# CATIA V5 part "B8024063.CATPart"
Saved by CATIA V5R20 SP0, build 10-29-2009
Part number: B8024063
Revision: 7
Definition: design
Nomenclature: B8024063
Source: made
Description: NOT SPECIFIED
Bounding box of the stored display mesh (mm): x -33 to 33, y -33 to 33, z -12 to 63
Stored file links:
  C:\Users\Utente\Desktop\3D files B802\B8024063.CATPart
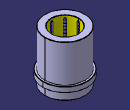
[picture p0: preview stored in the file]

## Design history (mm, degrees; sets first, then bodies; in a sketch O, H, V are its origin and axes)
Body1 "MANIFOLD_SOLID_BREP #38" (main body)
  Solid1: solid without history
Body2 "MANIFOLD_SOLID_BREP #76"
  Solid2: solid without history
Body3 "MANIFOLD_SOLID_BREP #114"
  Solid3: solid without history
Body4 "MANIFOLD_SOLID_BREP #152"
  Solid4: solid without history
Body5 "MANIFOLD_SOLID_BREP #190"
  Solid5: solid without history
Body6 "MANIFOLD_SOLID_BREP #228"
  Solid6: solid without history
Body7 "MANIFOLD_SOLID_BREP #266"
  Solid7: solid without history
Body8 "MANIFOLD_SOLID_BREP #304"
  Solid8: solid without history
Body9 "MANIFOLD_SOLID_BREP #2384"
  Solid9: solid without history
Body10 "MANIFOLD_SOLID_BREP #2422"
  Solid10: solid without history
Body11 "MANIFOLD_SOLID_BREP #2460"
  Solid11: solid without history
Body12 "MANIFOLD_SOLID_BREP #2498"
  Solid12: solid without history
Body13 "MANIFOLD_SOLID_BREP #2536"
  Solid13: solid without history
Body14 "MANIFOLD_SOLID_BREP #2574"
  Solid14: solid without history
Body15 "MANIFOLD_SOLID_BREP #2612"
  Solid15: solid without history
Body16 "MANIFOLD_SOLID_BREP #2650"
  Solid16: solid without history
Body17 "MANIFOLD_SOLID_BREP #2688"
  Solid17: solid without history
Body18 "MANIFOLD_SOLID_BREP #2726"
  Solid18: solid without history
Body19 "MANIFOLD_SOLID_BREP #2764"
  Solid19: solid without history
Body20 "MANIFOLD_SOLID_BREP #2802"
  Solid20: solid without history
Body21 "MANIFOLD_SOLID_BREP #2840"
  Solid21: solid without history
Body22 "MANIFOLD_SOLID_BREP #2878"
  Solid22: solid without history
Body23 "MANIFOLD_SOLID_BREP #2916"
  Solid23: solid without history
Body24 "MANIFOLD_SOLID_BREP #2954"
  Solid24: solid without history
Body25 "MANIFOLD_SOLID_BREP #2992"
  Solid25: solid without history
Body26 "MANIFOLD_SOLID_BREP #3030"
  Solid26: solid without history
Body27 "MANIFOLD_SOLID_BREP #3068"
  Solid27: solid without history
Body28 "MANIFOLD_SOLID_BREP #3106"
  Solid28: solid without history
Body29 "MANIFOLD_SOLID_BREP #3144"
  Solid29: solid without history
Body30 "MANIFOLD_SOLID_BREP #3182"
  Solid30: solid without history
Body31 "MANIFOLD_SOLID_BREP #3220"
  Solid31: solid without history
Body32 "MANIFOLD_SOLID_BREP #3258"
  Solid32: solid without history
Body33 "MANIFOLD_SOLID_BREP #3296"
  Solid33: solid without history
Body34 "MANIFOLD_SOLID_BREP #3334"
  Solid34: solid without history
Body35 "MANIFOLD_SOLID_BREP #3372"
  Solid35: solid without history
Body36 "MANIFOLD_SOLID_BREP #3410"
  Solid36: solid without history
Body37 "MANIFOLD_SOLID_BREP #3448"
  Solid37: solid without history
Body38 "MANIFOLD_SOLID_BREP #3486"
  Solid38: solid without history
Body39 "MANIFOLD_SOLID_BREP #3524"
  Solid39: solid without history
Body40 "MANIFOLD_SOLID_BREP #3562"
  Solid40: solid without history
Body41 "MANIFOLD_SOLID_BREP #3600"
  Solid41: solid without history
Body42 "MANIFOLD_SOLID_BREP #3638"
  Solid42: solid without history
Body43 "MANIFOLD_SOLID_BREP #3676"
  Solid43: solid without history
Body44 "MANIFOLD_SOLID_BREP #3714"
  Solid44: solid without history
Body45 "MANIFOLD_SOLID_BREP #3752"
  Solid45: solid without history
Body46 "MANIFOLD_SOLID_BREP #3790"
  Solid46: solid without history
Body47 "MANIFOLD_SOLID_BREP #3828"
  Solid47: solid without history
Body48 "MANIFOLD_SOLID_BREP #3866"
  Solid48: solid without history
Body49 "MANIFOLD_SOLID_BREP #3904"
  Solid49: solid without history
Body50 "MANIFOLD_SOLID_BREP #3942"
  Solid50: solid without history
Body51 "MANIFOLD_SOLID_BREP #3980"
  Solid51: solid without history
Body52 "MANIFOLD_SOLID_BREP #4018"
  Solid52: solid without history
Body53 "MANIFOLD_SOLID_BREP #4056"
  Solid53: solid without history
Body54 "MANIFOLD_SOLID_BREP #4094"
  Solid54: solid without history
Body55 "MANIFOLD_SOLID_BREP #4132"
  Solid55: solid without history
Body56 "MANIFOLD_SOLID_BREP #4170"
  Solid56: solid without history
Body57 "MANIFOLD_SOLID_BREP #4208"
  Solid57: solid without history
Body58 "MANIFOLD_SOLID_BREP #4246"
  Solid58: solid without history
Body59 "MANIFOLD_SOLID_BREP #4284"
  Solid59: solid without history
Body60 "MANIFOLD_SOLID_BREP #4322"
  Solid60: solid without history
Body61 "MANIFOLD_SOLID_BREP #4360"
  Solid61: solid without history
Body62 "MANIFOLD_SOLID_BREP #4398"
  Solid62: solid without history
Body63 "MANIFOLD_SOLID_BREP #4436"
  Solid63: solid without history
Body64 "MANIFOLD_SOLID_BREP #4474"
  Solid64: solid without history
Body65 "MANIFOLD_SOLID_BREP #4512"
  Solid65: solid without history
Body66 "MANIFOLD_SOLID_BREP #4550"
  Solid66: solid without history
Body67 "MANIFOLD_SOLID_BREP #4588"
  Solid67: solid without history
Body68 "MANIFOLD_SOLID_BREP #4626"
  Solid68: solid without history
Body69 "MANIFOLD_SOLID_BREP #4664"
  Solid69: solid without history
Body70 "MANIFOLD_SOLID_BREP #4702"
  Solid70: solid without history
Body71 "MANIFOLD_SOLID_BREP #4740"
  Solid71: solid without history
Body72 "MANIFOLD_SOLID_BREP #4778"
  Solid72: solid without history
Body73 "MANIFOLD_SOLID_BREP #4816"
  Solid73: solid without history
Body74 "MANIFOLD_SOLID_BREP #4854"
  Solid74: solid without history
Body75 "MANIFOLD_SOLID_BREP #4892"
  Solid75: solid without history
Body76 "MANIFOLD_SOLID_BREP #4930"
  Solid76: solid without history
Body77 "MANIFOLD_SOLID_BREP #4968"
  Solid77: solid without history
Body78 "MANIFOLD_SOLID_BREP #5006"
  Solid78: solid without history
Body79 "MANIFOLD_SOLID_BREP #5044"
  Solid79: solid without history
Body80 "MANIFOLD_SOLID_BREP #5082"
  Solid80: solid without history
Body81 "MANIFOLD_SOLID_BREP #5120"
  Solid81: solid without history
Body82 "MANIFOLD_SOLID_BREP #5158"
  Solid82: solid without history
Body83 "MANIFOLD_SOLID_BREP #5196"
  Solid83: solid without history
Body84 "MANIFOLD_SOLID_BREP #5234"
  Solid84: solid without history
Body85 "MANIFOLD_SOLID_BREP #5272"
  Solid85: solid without history
Body86 "MANIFOLD_SOLID_BREP #5310"
  Solid86: solid without history
Body87 "MANIFOLD_SOLID_BREP #5348"
  Solid87: solid without history
Body88 "MANIFOLD_SOLID_BREP #5386"
  Solid88: solid without history
Body89 "MANIFOLD_SOLID_BREP #5424"
  Solid89: solid without history
Body90 "MANIFOLD_SOLID_BREP #5462"
  Solid90: solid without history
Body91 "MANIFOLD_SOLID_BREP #5500"
  Solid91: solid without history
Body92 "MANIFOLD_SOLID_BREP #5538"
  Solid92: solid without history
Body93 "MANIFOLD_SOLID_BREP #5576"
  Solid93: solid without history
Body94 "MANIFOLD_SOLID_BREP #5614"
  Solid94: solid without history
Body95 "MANIFOLD_SOLID_BREP #5652"
  Solid95: solid without history
Body96 "MANIFOLD_SOLID_BREP #5690"
  Solid96: solid without history
Body97 "MANIFOLD_SOLID_BREP #5728"
  Solid97: solid without history
Body98 "MANIFOLD_SOLID_BREP #5766"
  Solid98: solid without history
Body99 "MANIFOLD_SOLID_BREP #5804"
  Solid99: solid without history
Body100 "MANIFOLD_SOLID_BREP #5842"
  Solid100: solid without history
Body101 "MANIFOLD_SOLID_BREP #5880"
  Solid101: solid without history
Body102 "MANIFOLD_SOLID_BREP #5918"
  Solid102: solid without history
Body103 "MANIFOLD_SOLID_BREP #5956"
  Solid103: solid without history
Body104 "MANIFOLD_SOLID_BREP #5994"
  Solid104: solid without history
Body105 "MANIFOLD_SOLID_BREP #6032"
  Solid105: solid without history
Body106 "MANIFOLD_SOLID_BREP #6070"
  Solid106: solid without history
Body107 "MANIFOLD_SOLID_BREP #6108"
  Solid107: solid without history
Body108 "MANIFOLD_SOLID_BREP #6146"
  Solid108: solid without history
Body109 "MANIFOLD_SOLID_BREP #6184"
  Solid109: solid without history
Body110 "MANIFOLD_SOLID_BREP #6222"
  Solid110: solid without history
Body111 "MANIFOLD_SOLID_BREP #6260"
  Solid111: solid without history
Body112 "MANIFOLD_SOLID_BREP #6298"
  Solid112: solid without history
Body113 "MANIFOLD_SOLID_BREP #6336"
  Solid113: solid without history
Body114 "MANIFOLD_SOLID_BREP #6374"
  Solid114: solid without history
Body115 "MANIFOLD_SOLID_BREP #6412"
  Solid115: solid without history
Body116 "MANIFOLD_SOLID_BREP #6450"
  Solid116: solid without history
Body117 "MANIFOLD_SOLID_BREP #6488"
  Solid117: solid without history
Body118 "MANIFOLD_SOLID_BREP #6526"
  Solid118: solid without history
Body119 "MANIFOLD_SOLID_BREP #6564"
  Solid119: solid without history
Body120 "MANIFOLD_SOLID_BREP #6602"
  Solid120: solid without history
Body121 "MANIFOLD_SOLID_BREP #6640"
  Solid121: solid without history
Body122 "MANIFOLD_SOLID_BREP #6678"
  Solid122: solid without history
Body123 "MANIFOLD_SOLID_BREP #6716"
  Solid123: solid without history
Body124 "MANIFOLD_SOLID_BREP #6754"
  Solid124: solid without history
Body125 "MANIFOLD_SOLID_BREP #6792"
  Solid125: solid without history
Body126 "MANIFOLD_SOLID_BREP #6830"
  Solid126: solid without history
Body127 "MANIFOLD_SOLID_BREP #6868"
  Solid127: solid without history
Body128 "MANIFOLD_SOLID_BREP #6906"
  Solid128: solid without history
Body129 "MANIFOLD_SOLID_BREP #6944"
  Solid129: solid without history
